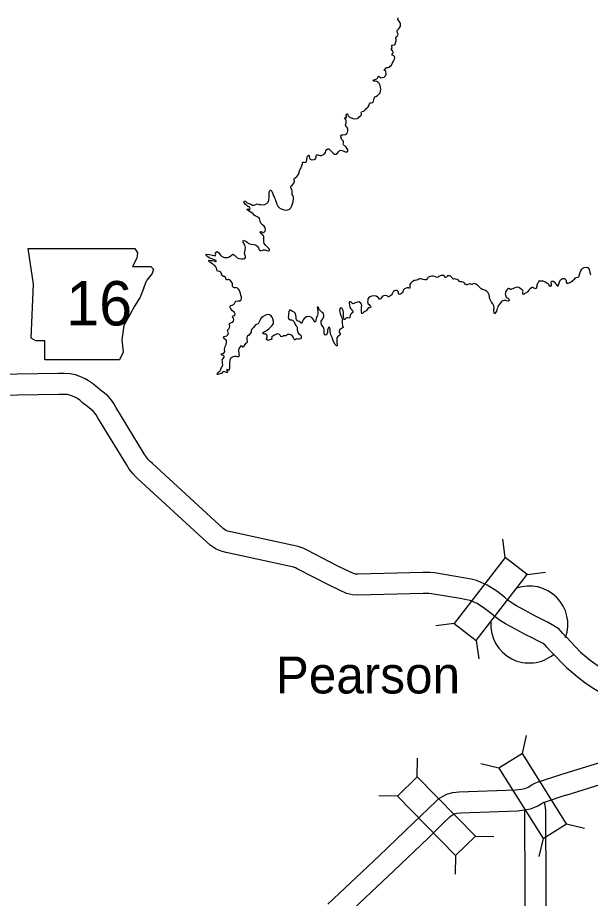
# Model space of a CAD drawing. Extents: x 1212896 to 1368412, y 378476 to 478763.
# Drawn here: x 1222342 to 1230517, y 456675 to 469257 of the extents above; entities that cross this region are included whole.
import ezdxf

# ---------------------------------------------------------------- set-up
doc = ezdxf.new("R2010")
doc.units = 0
for name, color, linetype in [('Level 10', 7, 'Continuous'), ('Level 11', 7, 'Continuous'), ('Level 20', 7, 'Continuous'), ('Level 21', 7, 'Continuous'), ('Level 24', 7, 'Continuous'), ('Level 9', 7, 'Continuous')]:
    doc.layers.add(name, color=color, linetype=linetype)

msp = doc.modelspace()

# ---------------------------------------------------------------- linework, layer by layer
at = {"layer": 'Level 10'}
for points in [[(1230177, 460402), (1230121, 460464), (1230070, 460522), (1229997, 460570), (1229905, 460621), (1229818, 460664), (1229743, 460702), (1229662, 460744), (1229594, 460784), (1229517, 460825), (1229455, 460858), (1229399, 460892), (1229343, 460931), (1229289, 460978), (1229181, 461061), (1229043, 461151), (1228959, 461189), (1228891, 461215), (1228814, 461234), (1228708, 461254), (1228292, 461324), (1228227, 461331), (1228125, 461331), (1227199, 461307), (1227164, 461308), (1227136, 461315), (1227065, 461349), (1226914, 461422), (1226467, 461653), (1226419, 461676), (1226345, 461701), (1226256, 461720), (1225385, 461911), (1225335, 461922), (1225314, 461930), (1225275, 461957), (1224265, 462885), (1224234, 462915), (1224209, 462941), (1224181, 462976), (1224150, 463027), (1223744, 463694), (1223713, 463745), (1223680, 463792), (1223632, 463848), (1223583, 463890), (1223527, 463936), (1223458, 463990), (1223412, 464028), (1223355, 464068), (1223304, 464097), (1223230, 464130), (1223169, 464153), (1223093, 464170), (1223005, 464175), (1222923, 464173), (1222034, 464157)], [(1229954, 460201), (1229897, 460264), (1229871, 460294), (1229841, 460314), (1229767, 460355), (1229684, 460395), (1229606, 460435), (1229516, 460481), (1229448, 460522), (1229375, 460560), (1229307, 460598), (1229236, 460639), (1229157, 460695), (1229099, 460746), (1229007, 460816), (1228899, 460887), (1228843, 460912), (1228800, 460929), (1228751, 460941), (1228656, 460959), (1228251, 461026), (1228210, 461031), (1228128, 461031), (1227196, 461007), (1227121, 461010), (1227036, 461031), (1226936, 461078), (1226779, 461154), (1226334, 461384), (1226306, 461398), (1226265, 461412), (1226193, 461427), (1225320, 461618), (1225249, 461634), (1225175, 461662), (1225088, 461721), (1224058, 462668), (1224022, 462703), (1223984, 462742), (1223934, 462804), (1223894, 462871), (1223487, 463539), (1223462, 463580), (1223443, 463607), (1223419, 463635), (1223390, 463660), (1223338, 463703), (1223270, 463756), (1223229, 463790), (1223196, 463814), (1223170, 463828), (1223116, 463852), (1223083, 463865), (1223052, 463872), (1222999, 463875), (1222929, 463873), (1222039, 463857)], [(1230174, 460405), (1230378, 460193), (1230459, 460126), (1230515, 460079), (1230616, 460004), (1230707, 459938), (1230797, 459886), (1230897, 459843), (1231025, 459779), (1231141, 459711), (1231266, 459645), (1231375, 459586), (1231466, 459539), (1231569, 459483), (1231661, 459428), (1231764, 459349), (1231860, 459264), (1231950, 459186), (1232081, 459074), (1232109, 459050)], [(1229958, 460197), (1230174, 459973), (1230266, 459896), (1230328, 459843), (1230439, 459761), (1230544, 459686), (1230662, 459618), (1230770, 459571), (1230882, 459515), (1230995, 459449), (1231124, 459380), (1231235, 459321), (1231326, 459274), (1231421, 459222), (1231492, 459180), (1231572, 459118), (1231663, 459038), (1231708, 458999)], [(1230081, 458438), (1231146, 458769)], [(1230170, 458151), (1231233, 458482)], [(1226770, 456592), (1227504, 457284), (1227991, 457753), (1228204, 457959), (1228311, 458061), (1228352, 458100), (1228406, 458132), (1228468, 458162), (1228549, 458185), (1228646, 458197), (1229450, 458226), (1229529, 458237), (1229582, 458246), (1229629, 458264), (1229631, 458265), (1229679, 458295), (1229722, 458321), (1229777, 458341), (1230080, 458438)], [(1226974, 456372), (1227711, 457067), (1228200, 457537), (1228411, 457743), (1228517, 457843), (1228535, 457860), (1228549, 457869), (1228575, 457881), (1228609, 457891), (1228670, 457898), (1229475, 457927), (1229574, 457941), (1229660, 457955), (1229749, 457988), (1229777, 458002), (1229836, 458039), (1229852, 458048), (1229874, 458056), (1230171, 458152)]]:
    msp.add_lwpolyline(points, dxfattribs=at)
at = {"layer": 'Level 11'}
for points in [[(1229968, 448537), (1229928, 451506), (1229914, 454127), (1229888, 456791), (1229882, 457934), (1229873, 458001), (1229863, 458053)], [(1229668, 448533), (1229628, 451503), (1229614, 454125), (1229588, 456789), (1229582, 457913), (1229578, 457942)]]:
    msp.add_lwpolyline(points, dxfattribs=at)
at = {"layer": 'Level 20'}
for p, q in [((1229299, 461542), (1229265, 461804)), ((1229299, 461542), (1228575, 460600)), ((1229613, 461300), (1229299, 461542)), ((1228889, 460359), (1229613, 461300)), ((1229613, 461300), (1229875, 461335)), ((1228575, 460600), (1228313, 460566)), ((1228575, 460600), (1228889, 460359)), ((1228889, 460359), (1228923, 460097)), ((1229546, 458746), (1229605, 459003)), ((1229546, 458746), (1229210, 458536)), ((1230176, 457739), (1229546, 458746)), ((1228046, 458413), (1228050, 458677)), ((1229210, 458536), (1228953, 458595)), ((1229210, 458536), (1229841, 457529)), ((1228046, 458413), (1227763, 458137)), ((1228875, 457562), (1228046, 458413)), ((1227763, 458137), (1227499, 458141)), ((1227763, 458137), (1228591, 457286)), ((1229841, 457529), (1230176, 457739)), ((1230176, 457739), (1230434, 457680)), ((1228591, 457286), (1228875, 457562)), ((1228875, 457562), (1229139, 457558)), ((1229841, 457529), (1229781, 457272)), ((1228591, 457286), (1228587, 457022))]:
    msp.add_line(p, q, dxfattribs=at)
at = {"layer": 'Level 21'}
for p, q in [((1222570, 465449), (1222494, 465957)), ((1222494, 465957), (1224016, 465956)), ((1224016, 465956), (1224051, 465898)), ((1224017, 465957), (1224017, 465957)), ((1224042, 465821), (1223983, 465703)), ((1224051, 465898), (1224042, 465821)), ((1223983, 465703), (1224245, 465703)), ((1224245, 465703), (1224279, 465661)), ((1224279, 465661), (1224262, 465601)), ((1224262, 465601), (1224186, 465508)), ((1222537, 464679), (1222570, 465449)), ((1224144, 465398), (1224186, 465508)), ((1224144, 465398), (1224093, 465263)), ((1224093, 465263), (1224008, 465136)), ((1224008, 465136), (1223949, 465018)), ((1223949, 465018), (1223856, 464857)), ((1223856, 464857), (1223831, 464654)), ((1222604, 464637), (1222537, 464679)), ((1223831, 464654), (1223848, 464476)), ((1222731, 464637), (1222604, 464637)), ((1222731, 464366), (1222731, 464637)), ((1223848, 464476), (1223797, 464366)), ((1223797, 464366), (1222731, 464366))]:
    msp.add_line(p, q, dxfattribs=at)
at = {"layer": 'Level 24'}
for start, end in [(340.5297, 109.4703), (176.7295, 309.1736)]:
    msp.add_arc((1229645, 460587), 550, start, end, dxfattribs=at)
at = {"layer": 'Level 9'}
for points in [[(1227426, 468348), (1227416, 468356), (1227423, 468367), (1227438, 468371), (1227456, 468375), (1227470, 468381), (1227480, 468391), (1227484, 468402), (1227489, 468414), (1227498, 468419), (1227510, 468407), (1227526, 468396), (1227544, 468399), (1227572, 468408), (1227592, 468426), (1227602, 468448), (1227604, 468464), (1227599, 468480), (1227591, 468494), (1227581, 468501), (1227573, 468508), (1227576, 468515), (1227586, 468522), (1227598, 468534), (1227605, 468542), (1227613, 468545), (1227631, 468543), (1227648, 468550), (1227659, 468562), (1227676, 468579), (1227693, 468610), (1227709, 468636), (1227720, 468663), (1227724, 468684), (1227719, 468701), (1227711, 468712), (1227694, 468722), (1227685, 468733), (1227692, 468742), (1227700, 468754), (1227702, 468765), (1227696, 468781), (1227686, 468789), (1227679, 468800), (1227680, 468812), (1227687, 468827), (1227682, 468842), (1227676, 468853), (1227683, 468861), (1227693, 468863), (1227724, 468868), (1227735, 468895), (1227743, 468924), (1227745, 468942), (1227741, 468957), (1227741, 468968), (1227753, 468985), (1227765, 468998), (1227772, 469015), (1227769, 469030), (1227765, 469041), (1227759, 469055), (1227759, 469073), (1227776, 469092), (1227794, 469110), (1227808, 469136), (1227809, 469167), (1227797, 469192), (1227787, 469205), (1227773, 469223), (1227765, 469237), (1227771, 469249), (1227780, 469257)], [(1226939, 467359), (1226950, 467363), (1226969, 467360), (1226989, 467352), (1227016, 467341), (1227032, 467338), (1227045, 467339), (1227055, 467345), (1227056, 467367), (1227042, 467391), (1227029, 467407), (1227011, 467423), (1227003, 467429), (1226993, 467440), (1226990, 467450), (1226992, 467467), (1226992, 467482), (1226986, 467496), (1226977, 467506), (1226966, 467521), (1226962, 467533), (1226959, 467548), (1226953, 467564), (1226954, 467573), (1226958, 467579), (1226964, 467583), (1226984, 467583), (1227020, 467587), (1227041, 467603), (1227050, 467618), (1227056, 467637), (1227057, 467662), (1227047, 467687), (1227036, 467694), (1227024, 467710), (1227023, 467726), (1227030, 467752), (1227033, 467774), (1227032, 467789), (1227025, 467797), (1227013, 467810), (1227009, 467820), (1227012, 467824), (1227027, 467825), (1227036, 467826), (1227038, 467835), (1227033, 467848), (1227031, 467863), (1227039, 467876), (1227044, 467882), (1227049, 467883), (1227052, 467879), (1227054, 467871), (1227061, 467854), (1227075, 467841), (1227093, 467829), (1227127, 467814), (1227155, 467811), (1227188, 467814), (1227207, 467826), (1227222, 467843), (1227234, 467854), (1227245, 467862), (1227248, 467870), (1227249, 467882), (1227247, 467895), (1227249, 467905), (1227260, 467917), (1227278, 467918), (1227290, 467923), (1227302, 467938), (1227310, 467953), (1227324, 467963), (1227347, 467980), (1227356, 467994), (1227358, 468004), (1227360, 468016), (1227362, 468030), (1227372, 468038), (1227390, 468040), (1227411, 468046), (1227422, 468063), (1227428, 468083), (1227432, 468101), (1227435, 468115), (1227441, 468124), (1227456, 468131), (1227477, 468142), (1227491, 468157), (1227515, 468181), (1227523, 468208), (1227525, 468234), (1227523, 468261), (1227516, 468288), (1227502, 468313), (1227490, 468327), (1227481, 468336), (1227467, 468342), (1227447, 468348), (1227440, 468347), (1227426, 468348)], [(1225946, 466787), (1225950, 466790), (1225959, 466791), (1225966, 466780), (1225974, 466763), (1225983, 466741), (1225988, 466726), (1225994, 466713), (1226005, 466695), (1226010, 466683), (1226019, 466664), (1226024, 466642), (1226032, 466618), (1226040, 466593), (1226050, 466573), (1226057, 466563), (1226074, 466545), (1226085, 466534), (1226105, 466525), (1226130, 466516), (1226149, 466511), (1226172, 466508), (1226197, 466511), (1226220, 466519), (1226240, 466537), (1226256, 466566), (1226267, 466598), (1226273, 466630), (1226279, 466664), (1226280, 466689), (1226273, 466710), (1226261, 466730), (1226258, 466741), (1226258, 466755), (1226259, 466770), (1226260, 466784), (1226257, 466801), (1226248, 466815), (1226240, 466826), (1226240, 466841), (1226247, 466852), (1226264, 466869), (1226288, 466894), (1226292, 466919), (1226290, 466935), (1226288, 466953), (1226294, 466963), (1226305, 466970), (1226328, 466987), (1226349, 467016), (1226358, 467043), (1226363, 467069), (1226374, 467091), (1226387, 467112), (1226395, 467130), (1226403, 467152), (1226407, 467170), (1226407, 467180), (1226408, 467185), (1226413, 467190), (1226419, 467191), (1226429, 467191), (1226442, 467188), (1226453, 467190), (1226464, 467202), (1226469, 467223), (1226472, 467242), (1226476, 467260), (1226480, 467275), (1226486, 467284), (1226497, 467290), (1226505, 467285), (1226504, 467272), (1226506, 467254), (1226518, 467234), (1226541, 467225), (1226575, 467228), (1226598, 467244), (1226601, 467270), (1226603, 467285), (1226611, 467295), (1226625, 467294), (1226655, 467288), (1226678, 467287), (1226699, 467294), (1226715, 467304), (1226735, 467332), (1226743, 467353), (1226755, 467374), (1226771, 467384), (1226784, 467382), (1226800, 467368), (1226819, 467350), (1226833, 467335), (1226848, 467317), (1226864, 467307), (1226886, 467306), (1226909, 467320), (1226924, 467339), (1226930, 467349), (1226939, 467359)], [(1225570, 466034), (1225562, 466049), (1225559, 466063), (1225566, 466075), (1225574, 466074), (1225601, 466061), (1225616, 466048), (1225631, 466033), (1225652, 466023), (1225681, 466019), (1225713, 466014), (1225736, 466009), (1225753, 465999), (1225766, 465985), (1225778, 465967), (1225786, 465950), (1225795, 465935), (1225814, 465927), (1225838, 465935), (1225852, 465940), (1225869, 465939), (1225897, 465929), (1225924, 465925), (1225936, 465931), (1225938, 465949), (1225911, 465974), (1225878, 466006), (1225862, 466030), (1225854, 466058), (1225858, 466087), (1225856, 466123), (1225850, 466139), (1225836, 466156), (1225824, 466168), (1225811, 466181), (1225805, 466189), (1225804, 466197), (1225814, 466203), (1225827, 466196), (1225852, 466185), (1225863, 466190), (1225877, 466206), (1225878, 466233), (1225873, 466253), (1225859, 466275), (1225835, 466298), (1225823, 466311), (1225813, 466322), (1225806, 466334), (1225803, 466349), (1225800, 466368), (1225795, 466387), (1225785, 466401), (1225770, 466408), (1225749, 466415), (1225731, 466425), (1225720, 466436), (1225706, 466454), (1225685, 466470), (1225663, 466482), (1225639, 466495), (1225623, 466507), (1225616, 466516), (1225618, 466522), (1225626, 466523), (1225637, 466518), (1225647, 466515), (1225661, 466526), (1225658, 466542), (1225641, 466555), (1225623, 466564), (1225612, 466573), (1225596, 466585), (1225584, 466599), (1225577, 466614), (1225573, 466626), (1225582, 466638), (1225595, 466636), (1225611, 466615), (1225619, 466609), (1225644, 466601), (1225671, 466590), (1225695, 466578), (1225710, 466577), (1225729, 466581), (1225743, 466589), (1225751, 466594), (1225763, 466597), (1225786, 466589), (1225808, 466585), (1225842, 466583), (1225872, 466588), (1225905, 466605), (1225917, 466621), (1225928, 466651), (1225932, 466686), (1225933, 466720), (1225932, 466742), (1225933, 466761), (1225939, 466777), (1225946, 466787)], [(1225524, 465315), (1225508, 465359), (1225495, 465377), (1225480, 465391), (1225469, 465398), (1225458, 465401), (1225446, 465398), (1225438, 465398), (1225422, 465402), (1225411, 465416), (1225410, 465436), (1225410, 465454), (1225404, 465470), (1225390, 465486), (1225379, 465500), (1225371, 465508), (1225361, 465515), (1225352, 465515), (1225342, 465512), (1225330, 465509), (1225317, 465514), (1225314, 465528), (1225313, 465540), (1225303, 465555), (1225296, 465560), (1225282, 465560), (1225264, 465566), (1225258, 465578), (1225256, 465591), (1225249, 465608), (1225240, 465619), (1225223, 465629), (1225203, 465635), (1225190, 465641), (1225187, 465657), (1225182, 465676), (1225171, 465696), (1225155, 465714), (1225139, 465726), (1225128, 465736), (1225114, 465746), (1225101, 465755), (1225087, 465765), (1225075, 465775), (1225072, 465778), (1225071, 465782), (1225070, 465788), (1225076, 465790), (1225093, 465789), (1225121, 465785), (1225142, 465780), (1225164, 465775), (1225172, 465771), (1225176, 465774), (1225174, 465786), (1225153, 465798), (1225126, 465808), (1225102, 465817), (1225078, 465824), (1225055, 465841), (1225043, 465855), (1225035, 465867), (1225029, 465874), (1225034, 465879), (1225075, 465872), (1225105, 465866), (1225142, 465858), (1225154, 465856), (1225163, 465855), (1225168, 465862), (1225169, 465876), (1225168, 465891), (1225172, 465904), (1225184, 465915), (1225211, 465903), (1225226, 465879), (1225238, 465863), (1225257, 465844), (1225293, 465828), (1225338, 465828), (1225367, 465841), (1225383, 465853), (1225395, 465864), (1225408, 465873), (1225414, 465875), (1225424, 465874), (1225436, 465865), (1225457, 465843), (1225474, 465825), (1225499, 465815), (1225537, 465810), (1225565, 465810), (1225584, 465816), (1225596, 465828), (1225594, 465844), (1225582, 465888), (1225590, 465934), (1225595, 465973), (1225590, 465994), (1225581, 466013), (1225570, 466034)], [(1229917, 465449), (1229925, 465436), (1229942, 465422), (1229948, 465420), (1229959, 465425), (1229962, 465438), (1229961, 465456), (1229959, 465478), (1229964, 465491), (1229972, 465493), (1229985, 465491), (1230000, 465481), (1230019, 465460), (1230032, 465439), (1230045, 465426), (1230056, 465425), (1230064, 465438), (1230070, 465461), (1230081, 465490), (1230091, 465509), (1230106, 465522), (1230120, 465528), (1230143, 465528), (1230154, 465524), (1230163, 465516), (1230169, 465508), (1230170, 465493), (1230171, 465484), (1230173, 465476), (1230180, 465463), (1230192, 465457), (1230202, 465461), (1230214, 465469), (1230229, 465476), (1230255, 465488), (1230265, 465500), (1230277, 465511), (1230292, 465521), (1230298, 465533), (1230313, 465543), (1230333, 465549), (1230350, 465554), (1230358, 465564), (1230363, 465588), (1230369, 465616), (1230380, 465640), (1230394, 465662), (1230407, 465676), (1230428, 465686), (1230461, 465690), (1230481, 465687), (1230491, 465675), (1230498, 465659), (1230503, 465638), (1230507, 465615), (1230515, 465594), (1230521, 465586)], [(1228843, 465455), (1228836, 465448), (1228831, 465444), (1228823, 465445), (1228802, 465453), (1228796, 465453), (1228781, 465450), (1228770, 465445), (1228758, 465439), (1228749, 465439), (1228730, 465451), (1228719, 465465), (1228709, 465474), (1228699, 465479), (1228682, 465481), (1228669, 465481), (1228660, 465482), (1228649, 465489), (1228635, 465504), (1228614, 465516), (1228598, 465521), (1228583, 465523), (1228565, 465521), (1228555, 465526), (1228547, 465535), (1228536, 465548), (1228520, 465561), (1228506, 465568), (1228492, 465570), (1228482, 465569), (1228473, 465566), (1228471, 465561), (1228466, 465554), (1228464, 465550), (1228457, 465545), (1228446, 465549), (1228436, 465563), (1228423, 465572), (1228403, 465575), (1228386, 465573), (1228348, 465560), (1228342, 465550), (1228330, 465545), (1228307, 465555), (1228274, 465563), (1228253, 465563), (1228232, 465559), (1228215, 465554), (1228199, 465545), (1228191, 465535), (1228182, 465521), (1228172, 465510), (1228155, 465510), (1228132, 465517), (1228102, 465524), (1228083, 465524), (1228068, 465520), (1228054, 465513), (1228035, 465508), (1228015, 465503), (1228002, 465499), (1227982, 465488), (1227967, 465476), (1227954, 465465), (1227948, 465458), (1227939, 465443), (1227938, 465424), (1227941, 465411), (1227942, 465405), (1227941, 465396), (1227938, 465393), (1227932, 465394), (1227921, 465396), (1227903, 465396), (1227888, 465392), (1227866, 465382), (1227851, 465369), (1227843, 465358), (1227840, 465343), (1227839, 465336), (1227838, 465330), (1227833, 465326), (1227823, 465321), (1227810, 465313), (1227805, 465308), (1227797, 465304), (1227788, 465302), (1227778, 465310), (1227776, 465331), (1227773, 465345), (1227764, 465353), (1227750, 465360), (1227733, 465357), (1227708, 465347), (1227696, 465331), (1227686, 465310), (1227680, 465296), (1227671, 465287), (1227656, 465277), (1227647, 465271), (1227640, 465267)], [(1229917, 465449), (1229906, 465456), (1229886, 465470), (1229866, 465482), (1229843, 465491), (1229777, 465494), (1229784, 465486), (1229765, 465469), (1229758, 465450), (1229753, 465433), (1229752, 465418), (1229750, 465405), (1229746, 465393), (1229741, 465384), (1229727, 465386), (1229712, 465394), (1229696, 465401), (1229679, 465401), (1229651, 465378), (1229635, 465359), (1229622, 465342), (1229605, 465327), (1229588, 465318), (1229574, 465308), (1229566, 465302), (1229558, 465304), (1229555, 465309), (1229553, 465324), (1229554, 465337), (1229558, 465348), (1229553, 465360), (1229546, 465364), (1229534, 465373), (1229512, 465393), (1229498, 465402), (1229473, 465404), (1229451, 465401), (1229427, 465392), (1229408, 465384), (1229392, 465376), (1229382, 465373), (1229375, 465373), (1229362, 465381), (1229352, 465388), (1229344, 465386), (1229335, 465377), (1229320, 465360), (1229309, 465346), (1229303, 465332), (1229300, 465309), (1229304, 465290), (1229308, 465278), (1229317, 465264), (1229330, 465254), (1229347, 465242), (1229355, 465233), (1229357, 465221), (1229355, 465208), (1229351, 465205), (1229345, 465206), (1229324, 465213), (1229309, 465216), (1229287, 465217), (1229268, 465210), (1229250, 465201), (1229238, 465187), (1229218, 465163), (1229208, 465150), (1229203, 465138), (1229198, 465124), (1229192, 465104), (1229184, 465085), (1229175, 465064), (1229166, 465047), (1229146, 465027), (1229143, 465037), (1229140, 465069), (1229140, 465095), (1229143, 465111), (1229140, 465139), (1229123, 465166), (1229104, 465194), (1229092, 465221), (1229083, 465240), (1229077, 465253), (1229076, 465274), (1229070, 465298), (1229059, 465323), (1229038, 465344), (1229020, 465360), (1228995, 465369), (1228983, 465373), (1228971, 465373), (1228957, 465381), (1228938, 465401), (1228920, 465419), (1228904, 465435), (1228884, 465447), (1228870, 465453), (1228853, 465457), (1228843, 465455)], [(1225447, 465191), (1225456, 465208), (1225488, 465212), (1225513, 465213), (1225531, 465224), (1225539, 465243), (1225535, 465266), (1225528, 465290), (1225524, 465315)], [(1227640, 465267), (1227631, 465270), (1227615, 465281), (1227588, 465285), (1227571, 465283), (1227550, 465276), (1227540, 465264), (1227526, 465245), (1227521, 465238), (1227515, 465235), (1227509, 465233), (1227506, 465234), (1227494, 465252), (1227461, 465278), (1227431, 465283), (1227391, 465276), (1227358, 465264), (1227341, 465237), (1227339, 465214), (1227336, 465195), (1227338, 465181), (1227346, 465170), (1227358, 465157), (1227370, 465146), (1227379, 465135), (1227381, 465118), (1227371, 465112), (1227353, 465110), (1227340, 465101), (1227329, 465085), (1227322, 465074), (1227311, 465065), (1227297, 465060), (1227284, 465049), (1227275, 465037), (1227266, 465031), (1227255, 465032), (1227248, 465051), (1227248, 465085), (1227252, 465122), (1227254, 465146), (1227251, 465165), (1227235, 465184), (1227214, 465195), (1227191, 465193), (1227160, 465184), (1227141, 465171), (1227126, 465170), (1227114, 465179), (1227109, 465188), (1227100, 465197), (1227081, 465197), (1227075, 465184), (1227077, 465149), (1227085, 465120), (1227099, 465098), (1227113, 465081), (1227123, 465069), (1227128, 465060), (1227129, 465052), (1227127, 465044), (1227108, 465030), (1227094, 465015), (1227087, 464999), (1227084, 464982), (1227082, 464973), (1227077, 464967), (1227069, 464963), (1227056, 464970), (1227035, 464967), (1227027, 464957), (1227014, 464944), (1227006, 464945), (1227001, 464951), (1226993, 464985), (1226994, 465040), (1226989, 465073), (1226975, 465102), (1226964, 465113), (1226946, 465107), (1226938, 465074), (1226945, 465031), (1226956, 465003), (1226966, 464982), (1226969, 464971), (1226974, 464958), (1226977, 464946), (1226975, 464928), (1226973, 464908), (1226974, 464895), (1226980, 464860), (1226984, 464846), (1226987, 464832), (1226973, 464820), (1226959, 464813), (1226949, 464807), (1226936, 464795), (1226930, 464776), (1226931, 464762), (1226941, 464751), (1226948, 464739)], [(1225499, 464530), (1225494, 464502), (1225495, 464485), (1225497, 464476), (1225500, 464449), (1225503, 464426), (1225500, 464415), (1225493, 464409), (1225476, 464410), (1225456, 464415), (1225433, 464415), (1225411, 464408), (1225382, 464387), (1225372, 464368), (1225365, 464321), (1225364, 464274), (1225364, 464246), (1225362, 464231), (1225359, 464220), (1225349, 464220), (1225343, 464226), (1225326, 464232), (1225327, 464221), (1225333, 464204), (1225338, 464191), (1225333, 464187), (1225321, 464187), (1225300, 464196), (1225286, 464202), (1225271, 464197), (1225268, 464186), (1225260, 464174), (1225249, 464172), (1225236, 464171), (1225226, 464166), (1225214, 464161), (1225197, 464158), (1225192, 464158), (1225194, 464173), (1225207, 464193), (1225221, 464208), (1225236, 464216), (1225243, 464236), (1225254, 464259), (1225266, 464279), (1225273, 464297), (1225268, 464324), (1225264, 464347), (1225263, 464369), (1225274, 464387), (1225288, 464408), (1225288, 464422), (1225276, 464431), (1225259, 464434), (1225251, 464441), (1225253, 464452), (1225268, 464460), (1225284, 464464), (1225297, 464481), (1225296, 464520), (1225306, 464558), (1225316, 464585), (1225323, 464610), (1225323, 464633), (1225316, 464649), (1225296, 464668), (1225282, 464688), (1225289, 464701), (1225308, 464705), (1225326, 464711), (1225341, 464725), (1225349, 464740), (1225350, 464756), (1225344, 464775), (1225338, 464790), (1225342, 464801), (1225355, 464811), (1225368, 464828), (1225369, 464850), (1225366, 464875), (1225367, 464885), (1225384, 464896), (1225405, 464906), (1225421, 464920), (1225429, 464943), (1225423, 464963), (1225410, 464981), (1225418, 464996), (1225441, 465003), (1225445, 465019), (1225432, 465047), (1225409, 465070), (1225390, 465090), (1225380, 465103), (1225375, 465121), (1225374, 465136), (1225385, 465146), (1225403, 465148), (1225425, 465159), (1225439, 465173), (1225447, 465191)], [(1226948, 464739), (1226943, 464719), (1226925, 464710), (1226910, 464699), (1226900, 464683), (1226897, 464663), (1226896, 464633), (1226899, 464612), (1226901, 464598), (1226902, 464584), (1226902, 464574), (1226900, 464569), (1226895, 464568), (1226874, 464588), (1226856, 464620), (1226842, 464652), (1226835, 464678), (1226825, 464697), (1226813, 464726), (1226808, 464751), (1226805, 464782), (1226802, 464804), (1226798, 464822), (1226789, 464833), (1226780, 464832), (1226771, 464810), (1226767, 464786), (1226763, 464758), (1226758, 464742), (1226747, 464724), (1226737, 464719), (1226724, 464727), (1226719, 464759), (1226719, 464792), (1226712, 464824), (1226700, 464846), (1226681, 464872), (1226672, 464894), (1226675, 464919), (1226700, 464954), (1226714, 464985), (1226714, 465008), (1226708, 465028), (1226688, 465046), (1226669, 465061), (1226656, 465076), (1226648, 465088), (1226639, 465108), (1226631, 465121), (1226619, 465122), (1226621, 465096), (1226626, 465053), (1226628, 465027), (1226624, 465004), (1226613, 464981), (1226603, 464959), (1226597, 464936), (1226595, 464916), (1226588, 464907), (1226578, 464911), (1226569, 464935), (1226556, 464954), (1226539, 464972), (1226517, 464984), (1226491, 464986), (1226463, 464980), (1226445, 464970), (1226430, 464960), (1226417, 464940), (1226408, 464922), (1226402, 464905), (1226396, 464893), (1226389, 464892), (1226376, 464908), (1226360, 464916), (1226346, 464918), (1226335, 464925), (1226320, 464943), (1226316, 464955), (1226319, 464976), (1226315, 465006), (1226302, 465033), (1226289, 465047), (1226267, 465059), (1226252, 465069), (1226240, 465079), (1226222, 465077), (1226212, 465053), (1226209, 465023), (1226206, 464998), (1226205, 464978), (1226214, 464955), (1226234, 464941), (1226253, 464937), (1226268, 464931), (1226288, 464909), (1226296, 464896), (1226304, 464875), (1226313, 464860), (1226325, 464844), (1226331, 464834)], [(1226331, 464834), (1226334, 464814), (1226334, 464796), (1226336, 464780), (1226342, 464760), (1226350, 464745), (1226371, 464729), (1226383, 464720), (1226388, 464709), (1226391, 464695), (1226389, 464682), (1226378, 464670), (1226358, 464664), (1226342, 464664), (1226323, 464670), (1226307, 464665), (1226307, 464655), (1226299, 464653), (1226286, 464666), (1226276, 464690), (1226260, 464715), (1226241, 464725), (1226222, 464729), (1226207, 464730), (1226194, 464729), (1226186, 464725), (1226181, 464714), (1226170, 464711), (1226160, 464711), (1226151, 464712), (1226132, 464709), (1226121, 464700), (1226112, 464697), (1226098, 464702), (1226087, 464719), (1226079, 464730), (1226067, 464736), (1226045, 464738), (1226006, 464720), (1225983, 464705), (1225969, 464695), (1225967, 464684), (1225968, 464670), (1225968, 464663), (1225956, 464657), (1225940, 464655), (1225929, 464649), (1225917, 464646), (1225902, 464655), (1225892, 464669), (1225898, 464683), (1225902, 464696), (1225903, 464714), (1225894, 464725), (1225878, 464733), (1225862, 464736), (1225846, 464742), (1225839, 464750), (1225852, 464763), (1225881, 464777), (1225908, 464797), (1225926, 464812), (1225953, 464833), (1225977, 464859), (1225992, 464888), (1225993, 464921), (1225984, 464953), (1225974, 464978), (1225955, 465003), (1225937, 465013), (1225915, 465016), (1225882, 465006), (1225847, 464987), (1225818, 464961), (1225800, 464928), (1225786, 464900), (1225775, 464884), (1225753, 464872), (1225737, 464866), (1225721, 464849), (1225702, 464827), (1225687, 464804), (1225676, 464782), (1225673, 464762), (1225659, 464742), (1225643, 464721), (1225625, 464704), (1225613, 464687), (1225614, 464658), (1225620, 464637), (1225619, 464624), (1225611, 464613), (1225594, 464601), (1225584, 464589), (1225576, 464573), (1225572, 464561), (1225567, 464550), (1225558, 464551), (1225549, 464564), (1225526, 464566), (1225499, 464530)]]:
    msp.add_lwpolyline(points, dxfattribs=at)

# ---------------------------------------------------------------- texts
at = {"layer": 'Level 21'}
msp.add_text('16', height=633.6, dxfattribs=at).set_placement((1223034, 464859))
at = {"layer": 'Level 24'}
msp.add_text('Pearson', height=528, dxfattribs=at).set_placement((1226027, 459602))

doc.saveas('drawing.dxf')
